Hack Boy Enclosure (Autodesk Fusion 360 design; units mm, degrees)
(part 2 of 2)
sketch "Sketch30" plane through (0, 0, 16) normal (0, 0, 1) x axis (-1, 0, 0)
  line L1 (-24.47, 19) -> (-24.47, 21)
  line L2 (-38.47, 18) -> (-25.47, 18)
  line L3 (-39.47, 21) -> (-39.47, 19)
  line L4 (-25.47, 22) -> (-38.47, 22)
  line L5 (4.83, -82.13) -> (4.83, -82.73)
  line L6 (4.18, -82.13) -> (4.83, -82.13)
  line L7 (4.18, -81.33) -> (4.18, -82.13)
  line L8 (4.83, -81.33) -> (4.18, -81.33)
  line L9 (4.83, 23.27) -> (4.83, -81.33)
  line L10 (-54.47, 24.57) -> (3.53, 24.57)
  line L11 (-68.77, -81.33) -> (-68.77, 10.27)
  line L12 (-68.12, -81.33) -> (-68.77, -81.33)
  line L13 (-68.12, -82.13) -> (-68.12, -81.33)
  line L14 (-68.77, -82.13) -> (-68.12, -82.13)
  line L15 (-68.77, -84.03) -> (-68.77, -82.13)
  line L16 (-66.87, -84.03) -> (-68.77, -84.03)
  line L17 (-66.87, -83.38) -> (-66.87, -84.03)
  line L18 (-66.07, -83.38) -> (-66.87, -83.38)
  line L19 (-66.07, -84.03) -> (-66.07, -83.38)
  line L20 (2.13, -84.03) -> (-66.07, -84.03)
  line L21 (2.13, -83.38) -> (2.13, -84.03)
  line L22 (2.93, -83.38) -> (2.13, -83.38)
  line L23 (2.93, -84.03) -> (2.93, -83.38)
  line L24 (3.53, -84.03) -> (2.93, -84.03)
  line L25 (-42.8004, 7.2572) -> (-42.3674, 7.5072)
  line L26 (-50.1883, 18.7534) -> (-43.6883, 7.4951)
  line L27 (-49.5174, 19.8913) -> (-49.9504, 19.6413)
  line L28 (-42.1295, 8.3951) -> (-48.6295, 19.6534)
  line L29 (-61.5174, 13.8913) -> (-61.9504, 13.6413)
  line L30 (-54.1295, 2.3951) -> (-60.6295, 13.6534)
  line L31 (-54.8004, 1.2572) -> (-54.3674, 1.5072)
  line L32 (-62.1883, 12.7534) -> (-55.6883, 1.4951)
  line L33 (-46.8004, 5.2572) -> (-46.3674, 5.5072)
  line L34 (-54.1883, 16.7534) -> (-47.6883, 5.4951)
  line L35 (-53.5174, 17.8913) -> (-53.9504, 17.6413)
  line L36 (-46.1295, 6.3951) -> (-52.6295, 17.6534)
  line L37 (-24.7171, -22.5934) -> (-24.7171, -9.5934)
  line L38 (-38.2171, -23.0934) -> (-25.2171, -23.0934)
  line L39 (-38.7171, -9.5934) -> (-38.7171, -22.5934)
  line L40 (-25.2171, -9.0934) -> (-38.2171, -9.0934)
  line L41 (-24.7171, -41.6434) -> (-24.7171, -28.6434)
  line L42 (-38.2171, -42.1434) -> (-25.2171, -42.1434)
  line L43 (-38.7171, -28.6434) -> (-38.7171, -41.6434)
  line L44 (-25.2171, -28.1434) -> (-38.2171, -28.1434)
  line L45 (-5.6671, -22.5934) -> (-5.6671, -9.5934)
  line L46 (-19.1671, -23.0934) -> (-6.1671, -23.0934)
  line L47 (-19.6671, -9.5934) -> (-19.6671, -22.5934)
  line L48 (-6.1671, -9.0934) -> (-19.1671, -9.0934)
  line L49 (-5.6671, -41.6434) -> (-5.6671, -28.6434)
  line L50 (-19.1671, -42.1434) -> (-6.1671, -42.1434)
  line L51 (-19.6671, -28.6434) -> (-19.6671, -41.6434)
  line L52 (-6.1671, -28.1434) -> (-19.1671, -28.1434)
  line L53 (-45.8897, -28.4519) -> (-45.8897, -15.4519)
  line L54 (-59.3897, -28.9519) -> (-46.3897, -28.9519)
  line L55 (-59.8897, -15.4519) -> (-59.8897, -28.4519)
  line L56 (-46.3897, -14.9519) -> (-59.3897, -14.9519)
  line L57 (-4.47, -77.4365) -> (-4.47, -49.4365)
  line L58 (-58.47, -78.4365) -> (-5.47, -78.4365)
  line L59 (-59.47, -56.4365) -> (-59.47, -77.4365)
  line L60 (-5.47, -48.4365) -> (-51.47, -48.4365)
  line L61 (0.88, -81.33) -> (-64.82, -81.33)
  line L62 (0.88, -82.13) -> (0.88, -81.33)
  line L63 (-64.82, -82.13) -> (0.88, -82.13)
  line L64 (-64.82, -81.33) -> (-64.82, -82.13)
  line L65 (-30.3393, -0.8376) -> (-29.9973, -1.7773)
  line L66 (-22.2241, 3.1803) -> (-29.7416, 0.4441)
  line L67 (-20.6003, 1.6429) -> (-20.9423, 2.5826)
  line L68 (-28.7155, -2.375) -> (-21.198, 0.3612)
  line L69 (-41.7162, -2.3752) -> (-34.198, 0.3612)
  line L70 (-43.3398, -0.8375) -> (-42.998, -1.7773)
  line L71 (-35.2241, 3.1803) -> (-42.742, 0.444)
  line L72 (-33.6003, 1.6429) -> (-33.9423, 2.5826)
  line L73 (-46.1883, 20.7534) -> (-39.6883, 9.4951)
  line L74 (-45.5174, 21.8913) -> (-45.9504, 21.6413)
  line L75 (-38.1295, 10.3951) -> (-44.6295, 21.6534)
  line L76 (-38.8004, 9.2572) -> (-38.3674, 9.5072)
  line L77 (-57.5174, 15.8913) -> (-57.9504, 15.6413)
  line L78 (-50.1295, 4.3951) -> (-56.6295, 15.6534)
  line L79 (-50.8004, 3.2572) -> (-50.3674, 3.5072)
  line L80 (-58.1883, 14.7534) -> (-51.6883, 3.4951)
  line L81 (-58.1295, 0.3951) -> (-64.6295, 11.6534)
  line L82 (-58.8004, -0.7428) -> (-58.3674, -0.4928)
  line L83 (-66.1883, 10.7534) -> (-59.6883, -0.5049)
  line L84 (-65.5174, 11.8913) -> (-65.9504, 11.6413)
  arc A1 centre (-25.47, 19) radius 1 clockwise from (-24.47, 19) to (-25.47, 18)
  arc A2 centre (-38.47, 19) radius 1 clockwise from (-38.47, 18) to (-39.47, 19)
  arc A3 centre (-38.47, 21) radius 1 clockwise from (-39.47, 21) to (-38.47, 22)
  arc A4 centre (-25.47, 21) radius 1 clockwise from (-25.47, 22) to (-24.47, 21)
  arc A5 centre (3.53, -82.73) radius 1.3 clockwise from (4.83, -82.73) to (3.53, -84.03)
  arc A6 centre (3.53, 23.27) radius 1.3 clockwise from (3.53, 24.57) to (4.83, 23.27)
  arc A7 centre (-54.47, 10.27) radius 14.3 clockwise from (-68.77, 10.27) to (-54.47, 24.57)
  arc A8 centre (-43.1254, 7.8201) radius 0.65 clockwise from (-42.8004, 7.2572) to (-43.6883, 7.4951)
  arc A9 centre (-49.6254, 19.0784) radius 0.65 clockwise from (-50.1883, 18.7534) to (-49.9504, 19.6413)
  arc A10 centre (-49.1924, 19.3284) radius 0.65 clockwise from (-49.5174, 19.8913) to (-48.6295, 19.6534)
  arc A11 centre (-42.6924, 8.0701) radius 0.65 clockwise from (-42.1295, 8.3951) to (-42.3674, 7.5072)
  arc A12 centre (-61.1924, 13.3284) radius 0.65 clockwise from (-61.5174, 13.8913) to (-60.6295, 13.6534)
  arc A13 centre (-54.6924, 2.0701) radius 0.65 clockwise from (-54.1295, 2.3951) to (-54.3674, 1.5072)
  arc A14 centre (-55.1254, 1.8201) radius 0.65 clockwise from (-54.8004, 1.2572) to (-55.6883, 1.4951)
  arc A15 centre (-61.6254, 13.0784) radius 0.65 clockwise from (-62.1883, 12.7534) to (-61.9504, 13.6413)
  arc A16 centre (-47.1254, 5.8201) radius 0.65 clockwise from (-46.8004, 5.2572) to (-47.6883, 5.4951)
  arc A17 centre (-53.6254, 17.0784) radius 0.65 clockwise from (-54.1883, 16.7534) to (-53.9504, 17.6413)
  arc A18 centre (-53.1924, 17.3284) radius 0.65 clockwise from (-53.5174, 17.8913) to (-52.6295, 17.6534)
  arc A19 centre (-46.6924, 6.0701) radius 0.65 clockwise from (-46.1295, 6.3951) to (-46.3674, 5.5072)
  circle C1 centre (2.53, -81.73) radius 1.45
  circle C2 centre (2.53, 3) radius 1.45
  circle C3 centre (-66.47, 3) radius 1.45
  circle C4 centre (-66.47, -81.73) radius 1.45
  arc A20 centre (-25.2171, -22.5934) radius 0.5 clockwise from (-24.7171, -22.5934) to (-25.2171, -23.0934)
  arc A21 centre (-38.2171, -22.5934) radius 0.5 clockwise from (-38.2171, -23.0934) to (-38.7171, -22.5934)
  arc A22 centre (-38.2171, -9.5934) radius 0.5 clockwise from (-38.7171, -9.5934) to (-38.2171, -9.0934)
  arc A23 centre (-25.2171, -9.5934) radius 0.5 clockwise from (-25.2171, -9.0934) to (-24.7171, -9.5934)
  arc A24 centre (-25.2171, -41.6434) radius 0.5 clockwise from (-24.7171, -41.6434) to (-25.2171, -42.1434)
  arc A25 centre (-38.2171, -41.6434) radius 0.5 clockwise from (-38.2171, -42.1434) to (-38.7171, -41.6434)
  arc A26 centre (-38.2171, -28.6434) radius 0.5 clockwise from (-38.7171, -28.6434) to (-38.2171, -28.1434)
  arc A27 centre (-25.2171, -28.6434) radius 0.5 clockwise from (-25.2171, -28.1434) to (-24.7171, -28.6434)
  arc A28 centre (-6.1671, -22.5934) radius 0.5 clockwise from (-5.6671, -22.5934) to (-6.1671, -23.0934)
  arc A29 centre (-19.1671, -22.5934) radius 0.5 clockwise from (-19.1671, -23.0934) to (-19.6671, -22.5934)
  arc A30 centre (-19.1671, -9.5934) radius 0.5 clockwise from (-19.6671, -9.5934) to (-19.1671, -9.0934)
  arc A31 centre (-6.1671, -9.5934) radius 0.5 clockwise from (-6.1671, -9.0934) to (-5.6671, -9.5934)
  arc A32 centre (-6.1671, -41.6434) radius 0.5 clockwise from (-5.6671, -41.6434) to (-6.1671, -42.1434)
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extrude "Extrude23" cut sketch "Sketch26" profile of L5 L6 L7 L8 L9 L10 L11 L12 against normal blind 3
fillet "Fillet10" radius 1.8
sketch "Sketch31" plane through (0, 84.73, 0) normal (0, 1, 0) x axis (-1, 0, 0)
  line L1 (3.53, 0.7) -> (-67.47, 0.7)
  line L2 (3.53, 13) -> (3.53, 0.7)
  line L3 (-67.47, 13) -> (3.53, 13)
  line L4 (-67.47, 0.7) -> (-67.47, 13)
  line L5 (-28.62, 5.9) -> (-35.32, 5.9)
  line L6 (-27.62, 4) -> (-27.62, 4.9)
  line L7 (-35.32, 3) -> (-28.62, 3)
  line L8 (-36.32, 4.9) -> (-36.32, 4)
  line L9 (-69.47, 0.7) -> (-69.47, 13)
  line L10 (3.53, 0) -> (-67.47, 0)
  arc A1 centre (-35.32, 4.9) radius 1 clockwise from (-36.32, 4.9) to (-35.32, 5.9)
  arc A2 centre (-28.62, 4.9) radius 1 clockwise from (-28.62, 5.9) to (-27.62, 4.9)
  arc A3 centre (-28.62, 4) radius 1 clockwise from (-27.62, 4) to (-28.62, 3)
  arc A4 centre (-35.32, 4) radius 1 clockwise from (-35.32, 3) to (-36.32, 4)
  point P6 (-36.32, 5.9)
  point P7 (-27.62, 5.9)
  point P8 (-36.32, 3)
  horizontal L5
  vertical L6
  horizontal L7
  vertical L8
  coincident P6 L5
  coincident P6 L8
  tangent L5 A1
  tangent L8 A1
  coincident P7 L5
  coincident P7 L6
  tangent L5 A2
  tangent L6 A2
  equal A1 A2
  tangent L6 A3
  tangent L7 A3
  coincident P8 L7
  coincident P8 L8
  tangent L7 A4
  tangent L8 A4
  equal A3 A4
  dimension "d242" distance P6 P7 = 8.7
  dimension "d243" distance P6 P8 = 2.9
  dimension "d244" distance L8 L9 = 33.15
  dimension "d245" distance L7 L10 = 3
  dimension "d246" radius A1 = 1
  dimension "d247" radius A3 = 1
extrude "Extrude24" cut sketch "Sketch31" profile of L5 L6 L7 L8 A1 A2 A3 A4 against normal blind 6
sketch "Sketch32" plane through (0, 84.73, 0) normal (0, 1, 0) x axis (-1, 0, 0)
  line L1 (-36.32, 4.9) -> (-36.32, 4)
  line L2 (-28.62, 5.9) -> (-35.32, 5.9)
  line L3 (-27.62, 4) -> (-27.62, 4.9)
  line L4 (-35.32, 3) -> (-28.62, 3)
  line L5 (3.53, 0.7) -> (-67.47, 0.7)
  line L6 (3.53, 13) -> (3.53, 0.7)
  line L7 (-67.47, 13) -> (3.53, 13)
  line L8 (-67.47, 0.7) -> (-67.47, 13)
  line L9 (-26.97, 7.7) -> (-36.97, 7.7)
  line L10 (-24.97, 3.2) -> (-24.97, 5.7)
  line L11 (-36.97, 1.2) -> (-26.97, 1.2)
  line L12 (-38.97, 5.7) -> (-38.97, 3.2)
  line L13 (-69.47, 0.7) -> (-69.47, 13)
  arc A1 centre (-35.32, 4.9) radius 1 clockwise from (-36.32, 4.9) to (-35.32, 5.9)
  arc A2 centre (-28.62, 4.9) radius 1 clockwise from (-28.62, 5.9) to (-27.62, 4.9)
  arc A3 centre (-28.62, 4) radius 1 clockwise from (-27.62, 4) to (-28.62, 3)
  arc A4 centre (-35.32, 4) radius 1 clockwise from (-35.32, 3) to (-36.32, 4)
  arc A5 centre (-36.97, 5.7) radius 2 clockwise from (-38.97, 5.7) to (-36.97, 7.7)
  arc A6 centre (-36.97, 3.2) radius 2 clockwise from (-36.97, 1.2) to (-38.97, 3.2)
  arc A7 centre (-26.97, 3.2) radius 2 clockwise from (-24.97, 3.2) to (-26.97, 1.2)
  arc A8 centre (-26.97, 5.7) radius 2 clockwise from (-26.97, 7.7) to (-24.97, 5.7)
  point P18 (-38.97, 7.7)
  point P20 (-38.97, 1.2)
  point P19 (-24.97, 1.2)
  horizontal L9
  vertical L10
  horizontal L11
  vertical L12
  coincident P18 L9
  coincident P18 L12
  tangent L9 A5
  tangent L12 A5
  coincident P20 L11
  coincident P20 L12
  tangent L11 A6
  tangent L12 A6
  equal A5 A6
  coincident P19 L10
  coincident P19 L11
  tangent L10 A7
  tangent L11 A7
  equal A5 A7
  tangent L9 A8
  tangent L10 A8
  equal A5 A8
  dimension "d250" distance P18 P20 = 6.5
  dimension "d251" distance L4 L11 = 1.8
  dimension "d252" distance P19 P20 = 14
  dimension "d253" distance L12 L13 = 30.5
  dimension "d254" radius A5 = 2
extrude "Extrude25" cut sketch "Sketch32" profile of L1 A1 L2 A2 L3 A3 L4 A4 L9 L10 L11 L12 A5 A6 A7 A8 against normal blind 5
extrude "Extrude26" add of existing geometry blind 3
extrude "Extrude27" add of existing geometry blind 3
extrude "Extrude28" add of existing geometry blind 3
extrude "Extrude29" add of existing geometry blind 3
surface_patch "SurfacePatch6"
surface_patch "SurfacePatch7"
surface_patch "SurfacePatch8"
surface_patch "SurfacePatch9"
surface_patch "SurfacePatch10"
extrude "Extrude30" add of existing geometry blind 3
extrude "Extrude31" add of existing geometry blind -3
extrude "Extrude32" add of existing geometry blind 3
extrude "Extrude33" add of existing geometry blind 3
